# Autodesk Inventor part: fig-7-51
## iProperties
Shininess: 77.0
Length Units: 11269
Angle Units: 11279
Time Units: 11290
Mass Units: 11283
Length Display Precision: 3
Angle Display Precision: 2
Created: 2002-01
Part Number: fig-7-51
Document SubType Name: Modeling
Designer: ***
Density: 1 g/cm^3
Density: 0.0
Volumn: 0.0
Area: 0.0
PropertySet Name: Model Information
Control State: 0
Master: False
Checked Out: False
Author: ***
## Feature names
1. Extrusion2
2. FaceDraft7
